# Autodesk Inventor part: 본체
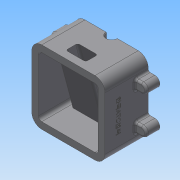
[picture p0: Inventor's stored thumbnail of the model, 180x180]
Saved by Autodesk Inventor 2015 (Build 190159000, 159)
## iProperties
Created: 2018-01
Part Number: 본체
Material: 일반
Document SubType Name: Modeling
Designer: user
Density: 1 g/cm^3
Appearance: 기본값
Author: user
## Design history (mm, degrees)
sketch "스케치1"
  geometry: L1 (55, 55)-(-55, 55); L2 (-55, 55)-(-55, -55); L3 (-55, -55)-(55, -55); L4 (55, -55)-(55, 55); 3 further points
  constraints: 8 end point, 2 midpoint, 2 parallel, 1 horizontal, 1 horizontal alignment, 1 perpendicular, 1 vertical alignment
  dimensions: "d0" = 110 distance of L1.start L1.end; "d1" = 110 distance of L1.end L2.end
extrude "돌출1" new body sketch "스케치1" distance "d2" = 65; taper "d3" = 0 deg
sketch "스케치2"
  geometry: L1 (-55, -55)-(55, -55) reference; L2 (55, -55)-(55, 55) reference; L3 (55, 55)-(-55, 55) reference; L4 (55, -55)-(55, 55) reference; L5 (65, -20.5)-(55, -20.5); L6 (65, -35.5)-(55, -35.5); L7 (65, 20.5)-(55, 20.5); L8 (65, 35.5)-(55, 35.5); L9 (55, 35.5)-(55, 20.5); L10 (55, -20.5)-(55, -35.5); A1 r 7.5 centre (65, 28) between (65, 20.5) and (65, 35.5); A2 r 7.5 centre (65, -28) between (65, -35.5) and (65, -20.5); 1 further point
  constraints: 12 end point, 4 point on circle, 4 point on line, 4 tangent, 3 perpendicular, 2 centre point, 2 collinear, 1 horizontal
  dimensions: "d4" = 56 distance of A1.centre A2.centre; "d5" = 15 diameter of A1; "d6" = 15 diameter of A2; "d7" = 10 distance from line of L2 A2.centre; "d8" = 27 distance from line of A2.centre L1; "d9" = 27 distance from line of L3 A1.centre
extrude "돌출2" join sketch "스케치2" distance "d10" = 20; taper "d11" = 0 deg
sketch "스케치3"
  geometry: L1 (-55, -55)-(55, -55) reference; L2 (55, -20.5)-(55, 20.5) reference; L3 (55, 55)-(-55, 55) reference; L4 (-55, 20.5)-(-55, -20.5) reference; L5 (-45, -45)-(45, -45); L6 (45, -45)-(45, 45); L7 (45, 45)-(-45, 45); L8 (-45, 45)-(-45, -45); 1 further point
  constraints: 8 end point, 2 parallel, 1 horizontal, 1 perpendicular
  dimensions: "d12" = 10 distance between parallel lines of L7 L3; "d13" = 10 distance between parallel lines of L4 L8; "d14" = 10 distance between parallel lines of L1 L5; "d15" = 10 distance between parallel lines of L2 L6
extrude "돌출3" cut sketch "스케치3" stored distance "d16" = 20; taper "d17" = 0 deg
sketch "스케치4"
  geometry: L1 (65, 45)-(65, -45) reference; L2 (65, -35)-(30, -35); L3 (30, -35)-(8.564, 45); L4 (65, 45)-(0, 45) reference; L5 (0, -45)-(0, 45) reference; L6 (0, -55)-(65, -55) reference; L7 (65, -35)-(65, 45); L8 (8.564, 45)-(65, 45); 1 further point
  constraints: 8 end point, 2 point on line, 1 collinear, 1 horizontal, 1 perpendicular
  dimensions: "d18" = 105 deg angle of L3 L4; "d19" = 30 distance from line of L2.end L5; "d20" = 20 distance between parallel lines of L6 L2
extrude "돌출4" join sketch "스케치4" stored distance "d21" = 50; taper "d22" = 0 deg
sketch "스케치5"
  geometry: L1 (-55, -55)-(55, -55) reference; L2 (55, 55)-(-55, 55) reference; L3 (0, -55)-(0, 55); L4 (0, -55)-(-7.5, -55); L5 (-7.5, -36)-(-16, -36); L6 (-16, -36)-(-16, -22); L7 (-16, -22)-(-20, -22); L8 (-20, -22)-(-20, 25); L9 (-20, 25)-(-15, 25); L10 (-15, 30)-(0, 30); L11 (-15, 30)-(-15, 25); L12 (-7.5, -36)-(-7.5, -55); 1 further point
  constraints: 20 end point, 3 perpendicular, 2 horizontal, 2 midpoint, 2 point on line, 2 vertical, 1 parallel
  dimensions: "d23" = 15 diameter of L12 L3; "d24" = 32 diameter of L6 L3; "d25" = 40 diameter of L8 L3; "d26" = 30 diameter of L11 L3; "d27" = 19 distance between parallel lines of L5 L1; "d28" = 14 distance of L5.end L6.end; "d29" = 47 distance of L7.end L8.end; "d30" = 5 distance of L10.start L9.end
revolve "회전1" sketch "스케치5" stored, may be unused: angle "d31" = 90 deg
sketch "스케치6"
  geometry: L1 (30, -35)-(8.564, 45) reference; L2 (31.157, -20)-(11.061, 55); L3 (0, 55)-(65, 55) reference; L4 (29.061, 55)-(39.243, 17); L5 (65, 22)-(45, 22) reference; L6 (65, -25)-(45, -25) reference; L7 (39.243, 17)-(65, 17); L8 (65, -20)-(31.157, -20); L9 (65, 22)-(65, -25) reference; L10 (65, -20)-(65, 17); L11 (29.061, 55)-(11.061, 55); 1 further point
  constraints: 12 end point, 4 point on line, 2 horizontal, 1 collinear, 1 parallel, 1 vertical
  dimensions: "d32" = 5 distance between parallel lines of L2 L1; "d33" = 75 deg angle of L3 L4; "d34" = 18 distance of L2.end L4.start; "d38" = 5 distance between parallel lines of L5 L7; "d39" = 5 distance between parallel lines of L6 L8
extrude "돌출5" cut sketch "스케치6" stored distance "d40" = 30; taper "d41" = 0 deg
hole "구멍1" diameter "d44" = 3.242; stored, may be unused: countersink angle "d48" = 90 deg, drill point angle "d50" = 118 deg; dims "d42" = 10, "d43" = 10, "d45" = 9, "d46" = 4, "d47" = 2, "d49" = 11
hole "구멍2" diameter "d53" = 3.242; stored, may be unused: countersink angle "d57" = 90 deg, drill point angle "d59" = 118 deg; dims "d51" = 10, "d52" = 10, "d54" = 9, "d55" = 4, "d56" = 2, "d58" = 11
fillet "모깎기1" dims "d60" = 15
fillet "모깎기2" dims "d61" = 1
fillet "모깎기3" dims "d62" = 3
fillet "모깎기4" dims "d63" = 3
chamfer "모따기1" distance "d64" = 1; stored, may be unused: second distance "d65" = 2, angle "d66" = 45 deg
fillet "모깎기5" dims "d67" = 5
fillet "모깎기6" dims "d68" = 3
fillet "모깎기7" dims "d69" = 3
fillet "모깎기8" dims "d70" = 3
fillet "모깎기9" dims "d71" = 3
fillet "모깎기10" dims "d72" = 3
fillet "모깎기11" dims "d73" = 3
fillet "모깎기13" dims "d75" = 3
fillet "모깎기14" dims "d76" = 3
node "작업 평면1"
sketch "스케치7"
  geometry: L1 (-15, 65)-(-15, 0) reference; L2 (95, 0)-(80, 0) reference; 2 further points
  constraints: 1 other
  dimensions: "d78" = 55 distance from line of L1 point (40, 20); "d79" = 20 distance from line of L2 point (40, 20)
feature "엠보싱1" sketch "스케치7" dims "d0" = 110, "d1" = 110, "d4" = 56, "d5" = 15, "d6" = 15, "d7" = 10, "d8" = 27, "d9" = 27, "d80" = 0.5, "d81" = 0
node "솔리드1"
mirror "대칭1"
mirror "대칭2"
other parameters: "d77" = 18.75
